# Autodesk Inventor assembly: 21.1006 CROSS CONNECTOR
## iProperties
Created: 2009-01
Part Number: 21.1006 CROSS CONNECTOR
Document SubType Name: Assembly
Designer: Administrator
Author: Administrator
